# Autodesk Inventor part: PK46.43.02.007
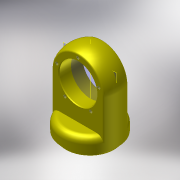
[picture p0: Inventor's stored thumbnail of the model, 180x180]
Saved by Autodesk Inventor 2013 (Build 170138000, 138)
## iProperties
Shininess: 20.0
Length Units: 11269
Angle Units: 11279
Time Units: 11290
Mass Units: 11283
Length Display Precision: 3
Angle Display Precision: 2
Created: 2001-08
Part Number: PK46.43.02.007
Material: Steel, Mild
Description: Крышка
Document SubType Name: Modeling
Designer: SOleg
Density: 7.86 g/cm^3
Mass: 21280.5 g
Surface Area: 1948.13 cm^2
Volume: 2707.44 cm^3
Density: 0.0
Volumn: 0.0
Area: 0.0
PropertySet Name: Model Information
Control State: 0
Master: False
Checked Out: True
Checked Out Date: 2008-10-09
Last Check In Date: 2008-10-09
Title: Крышка
Author: SOleg
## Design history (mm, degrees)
node "WorkPlane4"
node "WorkPlane3"
node "WorkPlane5"
node "WorkPlane6"
sketch "Sketch1"
  geometry: L1 (0, -102.5)-(0, 160); L2 (92.5, 67.5)-(92.5, -86.5); L3 (92.5, -86.5)-(82.5, -86.5); L4 (82.5, -86.5)-(82.5, -88.5); L5 (82.5, -88.5)-(80, -88.5); L6 (80, -88.5)-(80, -100.5); L7 (80, -100.5)-(78, -102.5); L8 (78, -102.5)-(0, -102.5); L9 (0, -102.5)-(0, 160); A1 r 92.5 centre (0, 67.5) between (92.5, 67.5) and (0, 160)
  constraints: 18 end point, 4 vertical, 3 horizontal, 2 point on circle, 1 centre point, 1 tangent, 1 other
  dimensions: "d4" = 170 distance of A1.centre L1.start; "d6" = 0 horizontal distance of A1.centre L1.end; "d8" = 2 horizontal distance of L6.end L7.end; "d10" = 2 horizontal distance of L6.end L7.end; "d12" = 14 vertical distance of L5.end L7.end; "d14" = 16 vertical distance of L2.end L7.end; "d16" = 80 horizontal distance of L5.end L1.start; "d18" = 82.5 horizontal distance of L4.end L1.start; "d20" = 92.5 horizontal distance of L2.end L1.start
revolve "RevolutionAngle1" sketch "Sketch1" stored, may be unused: angle "d21" = 360 deg
sketch "Sketch2"
  geometry: L1 through (81.534, 0) direction (1, 0)
  constraints: 2 horizontal, 1 end point
node "WorkAxis2"
node "WorkAxis3"
sketch "Sketch3"
  geometry: L1 (92.5, -56.5)-(92.5, -35.5); L2 (92.5, -35.5)-(87.5, -35.5); L3 (87.5, -35.5)-(87.5, -46.5); L4 (87.5, -46.5)-(40, -46.5); L5 (40, -46.5)-(40, -56.5); L6 (40, -56.5)-(92.5, -56.5); L7 (170.115, -56.5)-(-170.115, -56.5); C1 r 78 at (0, -102.5)
  constraints: 14 end point, 3 horizontal, 3 vertical, 1 centre point
  dimensions: "d24" = 5 distance of L1.end L2.end; "d26" = 52.5 distance of L5.end L1.start; "d28" = 10 distance of L4.end L5.end; "d30" = 21 distance of L1.start L1.end; "d32" = 46 vertical distance of L1.start C1.centre
revolve "RevolutionAngle4" sketch "Sketch3" stored, may be unused: angle "d33" = 360 deg
sketch "Sketch4"
  geometry: L1 (-92.5, -42.5)-(-92.5, 207.5); L2 (-40, -42.5)-(-92.5, -42.5); L3 (-40, 207.5)-(-40, -42.5); L4 (-92.5, 207.5)-(-40, 207.5); L5 (40, -42.5)-(40, 207.5); L6 (92.5, -42.5)-(40, -42.5); L7 (92.5, 207.5)-(92.5, -42.5); L8 (40, 207.5)-(92.5, 207.5); L9 (78, -102.5)-(-78, -102.5) reference; C1 r 78 at (0, -102.5)
  constraints: 16 end point, 4 horizontal, 4 vertical, 2 collinear, 1 centre point, 1 midpoint
  dimensions: "d35" = 80 distance of L3.start L5.end; "d37" = 52.5 distance of L5.end L7.start; "d39" = 52.5 distance of L1.end L3.start; "d41" = 250 distance of L7.start L6.start; "d43" = 60 vertical distance of L6.start C1.centre
extrude "ExtrusionMidplane1" cut sketch "Sketch4" stored distance "d44" = 185; taper "d45" = 0 deg
fillet "Fillet1" dims "d46" = 20
fillet "Fillet2" dims "d47" = 5
sketch "Sketch5"
  geometry: L1 (0, -102.5)-(0, -68.5); L2 (55, -102.5)-(0, -102.5); L3 (55, -68.5)-(55, -102.5); L4 (0, -68.5)-(55, -68.5); L5 (0, -163.865)-(0, 176.365); C1 r 78 at (0, -102.5)
  constraints: 10 end point, 2 horizontal, 2 vertical, 1 centre point, 1 coincident
  dimensions: "d49" = 34 distance of L3.start L2.start; "d51" = 55 distance of L2.start L1.start; "d53" = 0 vertical distance of L2.start C1.centre (derived)
revolve "RevolutionAngle5" sketch "Sketch5" stored, may be unused: angle "d54" = 360 deg
node "WorkAxis4"
fillet "Fillet3" dims "d55" = 3
sketch "Sketch6"
  geometry: L1 (27.5, -43.5)-(37.5, -37.726); L2 (27.5, -99.5)-(27.5, -43.5); L3 (37.5, -99.5)-(27.5, -99.5); L4 (37.5, -37.726)-(37.5, -99.5); L5 (37.5, -37.726)-(37.5, -99.5); C1 r 55 at (-0.5, -99.5)
  constraints: 10 end point, 2 vertical, 1 centre point, 1 horizontal
  dimensions: "d57" = 10 distance of L3.start L2.start; "d59" = 56 distance of L2.start L1.start; "d61" = 60 deg angle of L1 L4; "d63" = 0 vertical distance of L2.start C1.centre; "d120" = 38 distance from line of C1.centre L4
revolve "RevolutionAngle6" sketch "Sketch6" stored, may be unused: angle "d64" = 360 deg
sketch "Sketch7"
  geometry: L1 (0, 22.5)-(162.124, 22.5)
  constraints: 2 end point
node "WorkAxis5"
sketch "Sketch9"
  geometry: L1 (-19.728, -110)-(-19.728, 9.656) reference; L2 (60.467, -110)-(60.467, -155); L3 (-8.485, -132.404)-(60.467, -110); L4 (60.467, -110)-(17.853, -51.346); L5 (60.467, -110)-(103.081, -51.346); L6 (60.467, -110)-(129.419, -132.404); L7 (-17.533, 60)-(138.467, 60) reference; L8 (-19.533, 58)-(-19.533, 46) reference; C1 r 5 at (60.467, -182.5); C2 r 5 at (-8.485, -132.404); C3 r 5 at (17.853, -51.346); C4 r 5 at (103.081, -51.346); C5 r 5 at (129.419, -132.404); A1 r 80.195 centre (60.467, -110) between (-19.728, -110) and (140.662, -110) reference; A2 r 72.5 centre (60.467, -110) between (-8.485, -132.404) and (17.853, -51.346)
  constraints: 10 end point, 6 centre point, 4 equal radius, 4 point on circle, 1 coincident, 1 parallel
  dimensions: "d80" = 10 diameter of C1; "d83" = 72 deg angle of L3 L2; "d84" = 72 deg angle of L2 L6; "d85" = 144 deg angle of L4 L2; "d86" = 144 deg angle of L5 L2; "d87" = 145 diameter of A2; "d131" = 72.5 distance of C1.centre L2.start
hole "Hole1" sketch "Sketch9" at (17.853, -51.346), (103.081, -51.346), (129.419, -132.404), (60.467, -182.5), (-8.485, -132.404) diameter "d88" = 10; stored, may be unused: countersink angle "d92" = 82 deg, drill point angle "d94" = 118 deg; dims "d89" = 6, "d90" = 4, "d91" = 2, "d93" = 16
chamfer "Chamfer1" distance "d95" = 1; stored, may be unused: second distance "d96" = 1, angle "d132" = 45 deg
sketch "Эскиз10"
  geometry: L1 (-17.533, 60)-(138.467, 60) reference; L2 (140.467, 58)-(140.467, 46) reference; A1 r 80.195 centre (60.467, -110) between (-19.728, -110) and (140.662, -110) reference; 1 further point
  constraints: 1 coincident
hole "Отверстие2" sketch "Эскиз10" diameter "d101" = 125; stored, may be unused: countersink angle "d105" = 82 deg, drill point angle "d107" = 118 deg; dims "d102" = 6, "d103" = 129, "d104" = 2, "d106" = 40
node "РабПлоскость5"
node "РабОсь5"
mirror "ЗеркОтобр1"
feature "Резьба1" dims "d109" = 10, "d110" = 0
feature "Резьба2" dims "d111" = 10, "d112" = 0
feature "Резьба3" dims "d113" = 10, "d114" = 0
feature "Резьба4" dims "d115" = 10, "d116" = 0
feature "Резьба5" dims "d117" = 10, "d118" = 0
mirror "ЗеркОтобр2"
feature "Резьба6" dims "d121" = 10, "d122" = 0
feature "Резьба7" dims "d123" = 10, "d124" = 0
feature "Резьба8" dims "d125" = 10, "d126" = 0
feature "Резьба9" dims "d127" = 10, "d128" = 0
feature "Резьба10" dims "d129" = 10, "d130" = 0
body "Solid1"
other parameters: "d0" = -92.5, "d1" = -46, "d2" = -125, "d3" = 125 (derived), "d5" = 0 (derived), "d7" = 2 (derived), "d9" = 2 (derived), "d11" = 13 (derived), "d13" = 16 (derived), "d17" = 82.5 (derived), "d19" = 92.5 (derived), "d22" = 0, "d23" = 5 (derived), "d25" = 52.5 (derived), "d27" = 12.5 (derived), "d29" = 21.5 (derived), "d31" = 46 (derived), "d36" = 52.5 (derived), "d38" = 52.5 (derived), "d42" = 55 (derived), "d48" = 34 (derived), "d50" = 55 (derived), "d52" = 0 (derived), "d56" = 12.5 (derived), "d58" = 59 (derived), "d60" = 60 deg (derived), "d62" = 0 (derived), "d65" = 5 (derived), "d67" = 5 (derived), "d69" = 2 (derived), "d71" = 2 (derived), "d73" = 57.5 (derived), "d77" = 0 (derived)
